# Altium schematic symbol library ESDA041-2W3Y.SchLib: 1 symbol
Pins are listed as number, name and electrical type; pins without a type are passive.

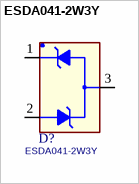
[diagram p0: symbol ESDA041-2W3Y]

## ESDA041-2W3Y
designator D?
footprint ST_SOT323-3L
pins: 1 K1, 2 A2, 3 A1K2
